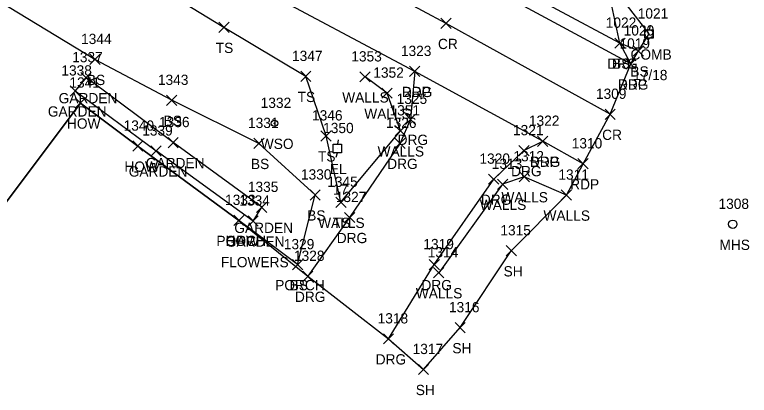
# Model space of a CAD drawing. Extents: x 1461855 to 1464118, y 556196 to 557441.
# Drawn here: x 1462535.4 to 1462678.7, y 556195.8 to 556269.9 of the extents above; entities that cross this region are included whole.
import ezdxf

# ---------------------------------------------------------------- set-up
doc = ezdxf.new("R2010")
doc.units = 0
for name, color, linetype in [('L_A', 7, 'Continuous'), ('L_C', 7, 'Continuous'), ('L_I', 7, 'Continuous'), ('L_TIC', 7, 'Continuous'), ('LAPB', 7, 'Continuous'), ('LBC', 7, 'Continuous'), ('LBF', 7, 'Continuous'), ('LELB', 7, 'Continuous'), ('LSOGP', 7, 'Continuous'), ('LWS', 7, 'Continuous'), ('P_A', 7, 'Continuous'), ('P_I', 7, 'Continuous'), ('P_TIC', 7, 'Continuous'), ('PET', 7, 'Continuous'), ('PRC', 7, 'Continuous'), ('R_A', 7, 'Continuous'), ('R_I', 7, 'Continuous'), ('R_TIC', 7, 'Continuous'), ('RDG', 7, 'Continuous'), ('U_A', 7, 'Continuous'), ('U_C', 7, 'Continuous'), ('U_I', 7, 'Continuous'), ('UEPT', 7, 'Continuous'), ('UP', 7, 'Continuous'), ('USMH', 7, 'Continuous'), ('UWV', 7, 'Continuous')]:
    doc.layers.add(name, color=color, linetype=linetype)

msp = doc.modelspace()

# ---------------------------------------------------------------- linework, layer by layer
at = {"layer": 'L_TIC'}
for points in [[(1462575.23, 556266.47), (1462577.23, 556268.47)], [(1462577.23, 556266.47), (1462575.23, 556268.47)], [(1462652.46, 556263.39), (1462654.46, 556265.39)], [(1462654.46, 556263.39), (1462652.46, 556265.39)], [(1462656.04, 556261.88), (1462658.04, 556263.88)], [(1462658.04, 556261.88), (1462656.04, 556263.88)], [(1462550.07, 556260.22), (1462552.07, 556262.22)], [(1462552.07, 556260.22), (1462550.07, 556262.22)], [(1462548.35, 556256.67), (1462550.35, 556258.67)], [(1462550.35, 556256.67), (1462548.35, 556258.67)], [(1462591.2, 556256.91), (1462593.2, 556258.91)], [(1462593.2, 556256.91), (1462591.2, 556258.91)], [(1462602.76, 556256.82), (1462604.76, 556258.82)], [(1462604.76, 556256.82), (1462602.76, 556258.82)], [(1462546.23, 556254.08), (1462548.23, 556256.08)], [(1462548.23, 556254.08), (1462546.23, 556256.08)], [(1462607.05, 556253.65), (1462609.05, 556255.65)], [(1462609.05, 556253.65), (1462607.05, 556255.65)], [(1462565.05, 556252.25), (1462567.05, 556254.25)], [(1462567.05, 556252.25), (1462565.05, 556254.25)], [(1462565.05, 556252.25), (1462567.05, 556254.25)], [(1462567.05, 556252.25), (1462565.05, 556254.25)], [(1462547.24, 556251.72), (1462549.24, 556253.72)], [(1462549.24, 556251.72), (1462547.24, 556253.72)], [(1462595.16, 556245.32), (1462597.16, 556247.32)], [(1462597.16, 556245.32), (1462595.16, 556247.32)], [(1462609.64, 556246.3), (1462611.64, 556248.3)], [(1462611.64, 556246.3), (1462609.64, 556248.3)], [(1462565.33, 556244.02), (1462567.33, 556246.02)], [(1462567.33, 556244.02), (1462565.33, 556246.02)], [(1462582.06, 556243.85), (1462584.06, 556245.85)], [(1462584.06, 556243.85), (1462582.06, 556245.85)], [(1462558.45, 556243.33), (1462560.45, 556245.33)], [(1462560.45, 556243.33), (1462558.45, 556245.33)], [(1462562, 556242.38), (1462564, 556244.38)], [(1462564, 556242.38), (1462562, 556244.38)], [(1462562, 556242.38), (1462564, 556244.38)], [(1462564, 556242.38), (1462562, 556244.38)], [(1462633.8, 556237.36), (1462635.8, 556239.36)], [(1462635.8, 556237.36), (1462633.8, 556239.36)], [(1462629.58, 556235.89), (1462631.58, 556237.89)], [(1462631.58, 556235.89), (1462629.58, 556237.89)], [(1462593.03, 556233.81), (1462595.03, 556235.81)], [(1462595.03, 556233.81), (1462593.03, 556235.81)], [(1462642.01, 556233.78), (1462644.01, 556235.78)], [(1462644.01, 556233.78), (1462642.01, 556235.78)], [(1462598.06, 556232.38), (1462600.06, 556234.38)], [(1462600.06, 556232.38), (1462598.06, 556234.38)], [(1462598.06, 556232.38), (1462600.06, 556234.38)], [(1462600.06, 556232.38), (1462598.06, 556234.38)], [(1462582.6, 556231.4), (1462584.6, 556233.4)], [(1462584.6, 556231.4), (1462582.6, 556233.4)], [(1462578.15, 556228.86), (1462580.15, 556230.86)], [(1462580.15, 556228.86), (1462578.15, 556230.86)], [(1462578.15, 556228.86), (1462580.15, 556230.86)], [(1462580.15, 556228.86), (1462578.15, 556230.86)], [(1462580.93, 556228.72), (1462582.93, 556230.72)], [(1462582.93, 556228.72), (1462580.93, 556230.72)], [(1462580.93, 556228.72), (1462582.93, 556230.72)], [(1462582.93, 556228.72), (1462580.93, 556230.72)], [(1462631.27, 556222.93), (1462633.27, 556224.93)], [(1462633.27, 556222.93), (1462631.27, 556224.93)], [(1462589.61, 556220.23), (1462591.61, 556222.23)], [(1462591.61, 556220.23), (1462589.61, 556222.23)], [(1462589.61, 556220.23), (1462591.61, 556222.23)], [(1462591.61, 556220.23), (1462589.61, 556222.23)], [(1462617.11, 556218.65), (1462619.11, 556220.65)], [(1462619.11, 556218.65), (1462617.11, 556220.65)], [(1462621.29, 556207.95), (1462623.29, 556209.95)], [(1462623.29, 556207.95), (1462621.29, 556209.95)], [(1462614.15, 556199.8), (1462616.15, 556201.8)], [(1462616.15, 556199.8), (1462614.15, 556201.8)]]:
    msp.add_lwpolyline(points, dxfattribs=at)
at = {"layer": 'LAPB'}
for points in [[(1462581.93, 556229.72), (1462583.6, 556232.4), (1462566.33, 556245.02), (1462549.35, 556257.67), (1462547.23, 556255.08), (1462563, 556243.38)], [(1462581.93, 556229.72), (1462563, 556243.38)]]:
    msp.add_lwpolyline(points, dxfattribs=at)
at = {"layer": 'LBC'}
msp.add_lwpolyline([(1462579.15, 556229.86), (1462559.45, 556244.33), (1462548.24, 556252.72), (1462531.2, 556230.03)], dxfattribs=at)
at = {"layer": 'LBF'}
msp.add_lwpolyline([(1462590.61, 556221.23), (1462579.15, 556229.86)], dxfattribs=at)
at = {"layer": 'LELB'}
for points in [[(1462657.04, 556262.88), (1462653.46, 556264.39), (1462629.14, 556277.47), (1462597.97, 556294.03), (1462580.33, 556303.87), (1462556.96, 556319.46), (1462539.52, 556332.25), (1462527.44, 556342.39), (1462506.25, 556364.14), (1462481.42, 556379.06), (1462468.44, 556386.07), (1462453.15, 556402.55), (1462451.23, 556401.93), (1462451.03, 556403.82)], [(1462599.06, 556233.38), (1462596.16, 556246.32), (1462592.2, 556257.91), (1462576.23, 556267.47), (1462557.62, 556278.83), (1462540.3, 556283.77), (1462528.89, 556296.86), (1462529.08, 556306.21), (1462517.11, 556315.38), (1462502.07, 556325.71), (1462477.93, 556342.63), (1462468.02, 556351.67), (1462460.8, 556357.54)], [(1462566.05, 556253.25), (1462551.07, 556261.22), (1462526.69, 556275.99), (1462519.12, 556289.53), (1462518.52, 556300.62), (1462520.17, 556306.41), (1462512.78, 556309.97), (1462497.67, 556320.06), (1462474.58, 556337.93), (1462471.37, 556338.06), (1462470.04, 556339.66), (1462464.04, 556350.54), (1462457.4, 556355.85)], [(1462590.61, 556221.23), (1462594.03, 556234.81), (1462583.06, 556244.85), (1462566.05, 556253.25)]]:
    msp.add_lwpolyline(points, dxfattribs=at)
at = {"layer": 'LSOGP'}
msp.add_lwpolyline([(1462531.2, 556230.03), (1462548.24, 556252.72), (1462559.45, 556244.33), (1462579.15, 556229.86), (1462592.59, 556218.96), (1462608.33, 556206.77), (1462615.15, 556200.8), (1462622.29, 556208.95), (1462632.27, 556223.93), (1462643.01, 556234.78), (1462646.26, 556240.88), (1462651.54, 556250.53), (1462655.57, 556260.33), (1462657.04, 556262.88), (1462659.12, 556266.18), (1462650.67, 556277.17)], dxfattribs=at)
at = {"layer": 'LWS'}
for points in [[(1462599.06, 556233.38), (1462610.64, 556247.3), (1462608.05, 556254.65), (1462603.76, 556257.82)], [(1462643.01, 556234.78), (1462634.8, 556238.36), (1462630.58, 556236.89), (1462618.11, 556219.65)]]:
    msp.add_lwpolyline(points, dxfattribs=at)
at = {"layer": 'P_TIC'}
for points in [[(1462618.54, 556267.24), (1462620.54, 556269.24)], [(1462620.54, 556267.24), (1462618.54, 556269.24)], [(1462654.57, 556259.33), (1462656.57, 556261.33)], [(1462656.57, 556259.33), (1462654.57, 556261.33)], [(1462612.44, 556257.88), (1462614.44, 556259.88)], [(1462614.44, 556257.88), (1462612.44, 556259.88)], [(1462650.54, 556249.53), (1462652.54, 556251.53)], [(1462652.54, 556249.53), (1462650.54, 556251.53)], [(1462637.39, 556244.28), (1462639.39, 556246.28)], [(1462639.39, 556244.28), (1462637.39, 556246.28)], [(1462645.26, 556239.88), (1462647.26, 556241.88)], [(1462647.26, 556239.88), (1462645.26, 556241.88)]]:
    msp.add_lwpolyline(points, dxfattribs=at)
at = {"layer": 'PET'}
for points in [[(1462655.57, 556260.33), (1462622.29, 556278.34), (1462596.05, 556293.11), (1462579.48, 556302.48), (1462555.03, 556317.39), (1462538.38, 556329.05), (1462522.59, 556339.78), (1462499.49, 556355.96), (1462479.91, 556370.2), (1462462.39, 556383.08), (1462450, 556394.49), (1462423.07, 556412.09), (1462414.08, 556417.65), (1462394.93, 556425.92), (1462382.48, 556434.45), (1462359.05, 556435.71), (1462354.93, 556436.4), (1462348.34, 556437.43), (1462333.33, 556438.52), (1462332.9, 556427.26)], [(1462646.26, 556240.88), (1462638.39, 556245.28), (1462613.44, 556258.88), (1462582.21, 556275.54), (1462550.05, 556294.22), (1462512.2, 556320.44), (1462479.05, 556344.07), (1462460.8, 556357.54), (1462433.62, 556376.17), (1462410.33, 556391.48), (1462383.13, 556406.1), (1462371.43, 556410.47), (1462364.34, 556412.93), (1462357.61, 556414.67), (1462347.76, 556416.01), (1462332.39, 556416.61), (1462332.9, 556427.26)]]:
    msp.add_lwpolyline(points, dxfattribs=at)
at = {"layer": 'PRC'}
msp.add_lwpolyline([(1462651.54, 556250.53), (1462619.54, 556268.24), (1462587.25, 556285.55), (1462556.86, 556302.79), (1462518.1, 556329.05), (1462484.17, 556354), (1462438.09, 556386.5), (1462416.23, 556401.26), (1462387.08, 556415.75), (1462366.36, 556422.8), (1462356.92, 556424.51), (1462339.71, 556426.54), (1462332.9, 556427.26)], dxfattribs=at)
at = {"layer": 'R_TIC'}
for points in [[(1462652.46, 556263.39), (1462654.46, 556265.39)], [(1462654.46, 556263.39), (1462652.46, 556265.39)], [(1462654.57, 556259.33), (1462656.57, 556261.33)], [(1462656.57, 556259.33), (1462654.57, 556261.33)], [(1462612.44, 556257.88), (1462614.44, 556259.88)], [(1462614.44, 556257.88), (1462612.44, 556259.88)], [(1462611.61, 556248.55), (1462613.61, 556250.55)], [(1462613.61, 556248.55), (1462611.61, 556250.55)], [(1462609.58, 556243.87), (1462611.58, 556245.87)], [(1462611.58, 556243.87), (1462609.58, 556245.87)], [(1462637.39, 556244.28), (1462639.39, 556246.28)], [(1462639.39, 556244.28), (1462637.39, 556246.28)], [(1462633.73, 556242.45), (1462635.73, 556244.45)], [(1462635.73, 556242.45), (1462633.73, 556244.45)], [(1462627.84, 556236.89), (1462629.84, 556238.89)], [(1462629.84, 556236.89), (1462627.84, 556238.89)], [(1462599.74, 556229.42), (1462601.74, 556231.42)], [(1462601.74, 556229.42), (1462599.74, 556231.42)], [(1462616.25, 556220.24), (1462618.25, 556222.24)], [(1462618.25, 556220.24), (1462616.25, 556222.24)], [(1462591.59, 556217.96), (1462593.59, 556219.96)], [(1462593.59, 556217.96), (1462591.59, 556219.96)], [(1462607.33, 556205.77), (1462609.33, 556207.77)], [(1462609.33, 556205.77), (1462607.33, 556207.77)]]:
    msp.add_lwpolyline(points, dxfattribs=at)
at = {"layer": 'RDG'}
for points in [[(1462655.57, 556260.33), (1462653.46, 556264.39), (1462650.67, 556277.17), (1462658.62, 556291.97)], [(1462613.44, 556258.88), (1462612.61, 556249.55), (1462610.58, 556244.87), (1462600.74, 556230.42), (1462592.59, 556218.96)], [(1462608.33, 556206.77), (1462617.25, 556221.24), (1462628.84, 556237.89), (1462634.73, 556243.45), (1462638.39, 556245.28)]]:
    msp.add_lwpolyline(points, dxfattribs=at)
at = {"layer": 'UEPT'}
for p, q in [((1462597.52, 556243.02), (1462597.52, 556244.69)), ((1462597.52, 556244.69), (1462599.19, 556244.69)), ((1462598.52, 556245.52), (1462598.36, 556244.69)), ((1462599.19, 556244.69), (1462599.19, 556243.02)), ((1462599.19, 556243.02), (1462597.52, 556243.02)), ((1462598.11, 556242.19), (1462598.36, 556243.02)), ((1462598.36, 556243.86), (1462598.36, 556243.86))]:
    msp.add_line(p, q, dxfattribs=at)
at = {"layer": 'UP'}
for p, q in [((1462658.29, 556265.35), (1462658.29, 556267.01)), ((1462658.29, 556267.01), (1462659.95, 556267.01)), ((1462659.37, 556267.85), (1462659.12, 556267.01)), ((1462659.95, 556267.01), (1462659.95, 556265.35)), ((1462659.12, 556266.18), (1462659.12, 556266.18)), ((1462659.95, 556265.35), (1462658.29, 556265.35)), ((1462658.87, 556264.51), (1462659.12, 556265.35))]:
    msp.add_line(p, q, dxfattribs=at)
msp.add_circle((1462659.12, 556266.18), 0.833, dxfattribs=at)
at = {"layer": 'USMH'}
for p, q in [((1462675.44, 556229.09), (1462675.44, 556229.09)), ((1462676.27, 556229.09), (1462676.27, 556229.09))]:
    msp.add_line(p, q, dxfattribs=at)
msp.add_circle((1462675.44, 556229.09), 0.833, dxfattribs=at)
at = {"layer": 'UWV'}
for radius in [0.625, 0.0833]:
    msp.add_circle((1462586.09, 556248.77), radius, dxfattribs=at)

# ---------------------------------------------------------------- texts
at = {"layer": 'L_A'}
for s, p in [('TS', (1462574.64, 556262.47)), ('BS', (1462651.91, 556259.39)), ('BS', (1462655.48, 556257.88)), ('BS', (1462549.51, 556256.22)), ('GARDEN', (1462544.01, 556252.67)), ('TS', (1462590.61, 556252.91)), ('WALLS', (1462599.3, 556252.82)), ('GARDEN', (1462541.9, 556250.08)), ('WALLS', (1462603.6, 556249.65)), ('BS', (1462564.49, 556248.25)), ('BS', (1462564.49, 556248.25)), ('HOW', (1462545.63, 556247.72)), ('WALLS', (1462606.19, 556242.3)), ('TS', (1462594.57, 556241.32)), ('HOW', (1462556.83, 556239.33)), ('GARDEN', (1462561, 556240.02)), ('BS', (1462581.5, 556239.85)), ('GARDEN', (1462557.67, 556238.38)), ('GARDEN', (1462557.67, 556238.38)), ('WALLS', (1462630.34, 556233.36)), ('WALLS', (1462626.13, 556231.89)), ('BS', (1462592.47, 556229.81)), ('WALLS', (1462638.55, 556229.78)), ('WALLS', (1462594.6, 556228.38)), ('TS', (1462597.47, 556228.38)), ('GARDEN', (1462578.26, 556227.4)), ('PORCH', (1462574.77, 556224.86)), ('GARDEN', (1462576.6, 556224.72)), ('GARDEN', (1462576.6, 556224.72)), ('HOW', (1462576.54, 556224.86)), ('SH', (1462630.76, 556218.93)), ('PORCH', (1462586.23, 556216.23)), ('BS', (1462589.05, 556216.23)), ('WALLS', (1462613.65, 556214.65)), ('SH', (1462620.78, 556203.95)), ('SH', (1462613.64, 556195.8))]:
    msp.add_text(s, height=2, dxfattribs=at).set_placement(p)
at = {"layer": 'L_C'}
msp.add_text('FLOWERS', height=2, dxfattribs=at).set_placement((1462575.63, 556220.72))
msp.add_text('FLOWERS', height=2, dxfattribs=at).set_placement((1462575.63, 556220.72))
at = {"layer": 'L_I'}
for s, p in [('1022', (1462650.69, 556267.39)), ('1020', (1462654.18, 556265.88)), ('1344', (1462548.38, 556264.22)), ('1347', (1462589.51, 556260.91)), ('1353', (1462601.07, 556260.82)), ('1337', (1462546.65, 556260.67)), ('1338', (1462544.54, 556258.08)), ('1352', (1462605.36, 556257.65)), ('1341', (1462546.11, 556255.72)), ('1343', (1462563.36, 556256.25)), ('1343', (1462563.36, 556256.25)), ('1346', (1462593.41, 556249.32)), ('1351', (1462608.52, 556250.3)), ('1336', (1462563.58, 556248.02)), ('1331', (1462580.93, 556247.85)), ('1340', (1462556.67, 556247.33)), ('1339', (1462560.3, 556246.38)), ('1339', (1462560.3, 556246.38)), ('1312', (1462632.68, 556241.36)), ('1313', (1462628.46, 556239.89)), ('1330', (1462591.25, 556237.81)), ('1311', (1462641.45, 556237.78)), ('1345', (1462596.37, 556236.38)), ('1345', (1462596.37, 556236.38)), ('1335', (1462580.9, 556235.4)), ('1333', (1462576.46, 556232.86)), ('1333', (1462576.46, 556232.86)), ('1334', (1462579.24, 556232.72)), ('1334', (1462579.24, 556232.72)), ('1315', (1462630.14, 556226.93)), ('1329', (1462587.91, 556224.23)), ('1329', (1462587.91, 556224.23)), ('1314', (1462615.98, 556222.65)), ('1316', (1462620.11, 556211.95)), ('1317', (1462613.02, 556203.8))]:
    msp.add_text(s, height=2, dxfattribs=at).set_placement(p)
at = {"layer": 'P_A'}
for s, p in [('CR', (1462617.97, 556263.24)), ('RDP', (1462653.06, 556255.33)), ('RDP', (1462610.92, 556253.88)), ('CR', (1462649.98, 556245.53)), ('RDP', (1462635.88, 556240.28)), ('RDP', (1462643.75, 556235.88))]:
    msp.add_text(s, height=2, dxfattribs=at).set_placement(p)
at = {"layer": 'P_I'}
for s, p in [('1019', (1462653.36, 556263.33)), ('1323', (1462610.74, 556261.88)), ('1309', (1462648.77, 556253.53)), ('1322', (1462635.7, 556248.28)), ('1310', (1462644.05, 556243.88))]:
    msp.add_text(s, height=2, dxfattribs=at).set_placement(p)
at = {"layer": 'R_A'}
for p in [(1462650.95, 556259.39), (1462653.06, 556255.33), (1462610.92, 556253.88), (1462610.1, 556244.55), (1462608.07, 556239.87), (1462635.88, 556240.28), (1462632.22, 556238.45), (1462626.33, 556232.89), (1462598.23, 556225.42), (1462614.74, 556216.24), (1462590.08, 556213.96), (1462605.82, 556201.77)]:
    msp.add_text('DRG', height=2, dxfattribs=at).set_placement(p)
at = {"layer": 'R_I'}
for s, p in [('1022', (1462650.69, 556267.39)), ('1019', (1462653.36, 556263.33)), ('1323', (1462610.74, 556261.88)), ('1325', (1462609.91, 556252.55)), ('1326', (1462607.83, 556247.87)), ('1322', (1462635.7, 556248.28)), ('1321', (1462632.6, 556246.45)), ('1320', (1462626.06, 556240.89)), ('1327', (1462598.05, 556233.42)), ('1319', (1462615.12, 556224.24)), ('1328', (1462589.89, 556221.96)), ('1318', (1462606.2, 556209.77))]:
    msp.add_text(s, height=2, dxfattribs=at).set_placement(p)
at = {"layer": 'U_A'}
for s, p in [('COMB', (1462655.51, 556261.18)), ('WSO', (1462583.42, 556243.77)), ('EL', (1462596.89, 556238.86)), ('MHS', (1462672.85, 556224.09))]:
    msp.add_text(s, height=2, dxfattribs=at).set_placement(p)
at = {"layer": 'U_C'}
for s, p in [('17/18', (1462656.02, 556257.18)), ('17', (1462597.46, 556234.86))]:
    msp.add_text(s, height=2, dxfattribs=at).set_placement(p)
at = {"layer": 'U_I'}
for s, p in [('1021', (1462656.92, 556269.18)), ('1332', (1462583.4, 556251.77)), ('1350', (1462595.58, 556246.86)), ('1308', (1462672.67, 556232.09))]:
    msp.add_text(s, height=2, dxfattribs=at).set_placement(p)

doc.saveas('drawing.dxf')
